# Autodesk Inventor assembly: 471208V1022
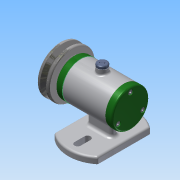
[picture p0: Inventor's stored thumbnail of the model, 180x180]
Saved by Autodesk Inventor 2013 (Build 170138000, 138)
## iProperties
Created: 2017-12
Part Number: 471208V1022
Document SubType Name: Assembly
Designer: Administrator
Author: Administrator
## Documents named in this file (14)
- C:\Users\Administrator\Desktop\471208V1022\471208V1022.iam
- C:\Users\Administrator\Desktop\471208V1022\본체.ipt
- C:\Users\Administrator\Desktop\471208V1022\V벨트풀리.ipt
- C:\Users\Administrator\Desktop\471208V1022\고무캡.ipt
- C:\Users\Administrator\Desktop\471208V1022\너트 M 8.ipt
- C:\Users\Administrator\Desktop\471208V1022\뒤커버.ipt
- C:\Users\Administrator\Desktop\471208V1022\베어링 15 x 32 x 9.ipt
- C:\Users\Administrator\Desktop\471208V1022\볼트 M4 x 12.ipt
- C:\Users\Administrator\Desktop\471208V1022\스프링와셔 8.ipt
- C:\Users\Administrator\Desktop\471208V1022\앞커버.ipt
- C:\Users\Administrator\Desktop\471208V1022\오일 실 15 25 7.ipt
- C:\Users\Administrator\Desktop\471208V1022\와셔 8x17.ipt
- C:\Users\Administrator\Desktop\471208V1022\축.ipt
- C:\Users\Administrator\Desktop\471208V1022\키 3 x 3 x 12.ipt
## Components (2 placed, 2 different names)
1. V벨트풀리:1
2. 고무캡:1
